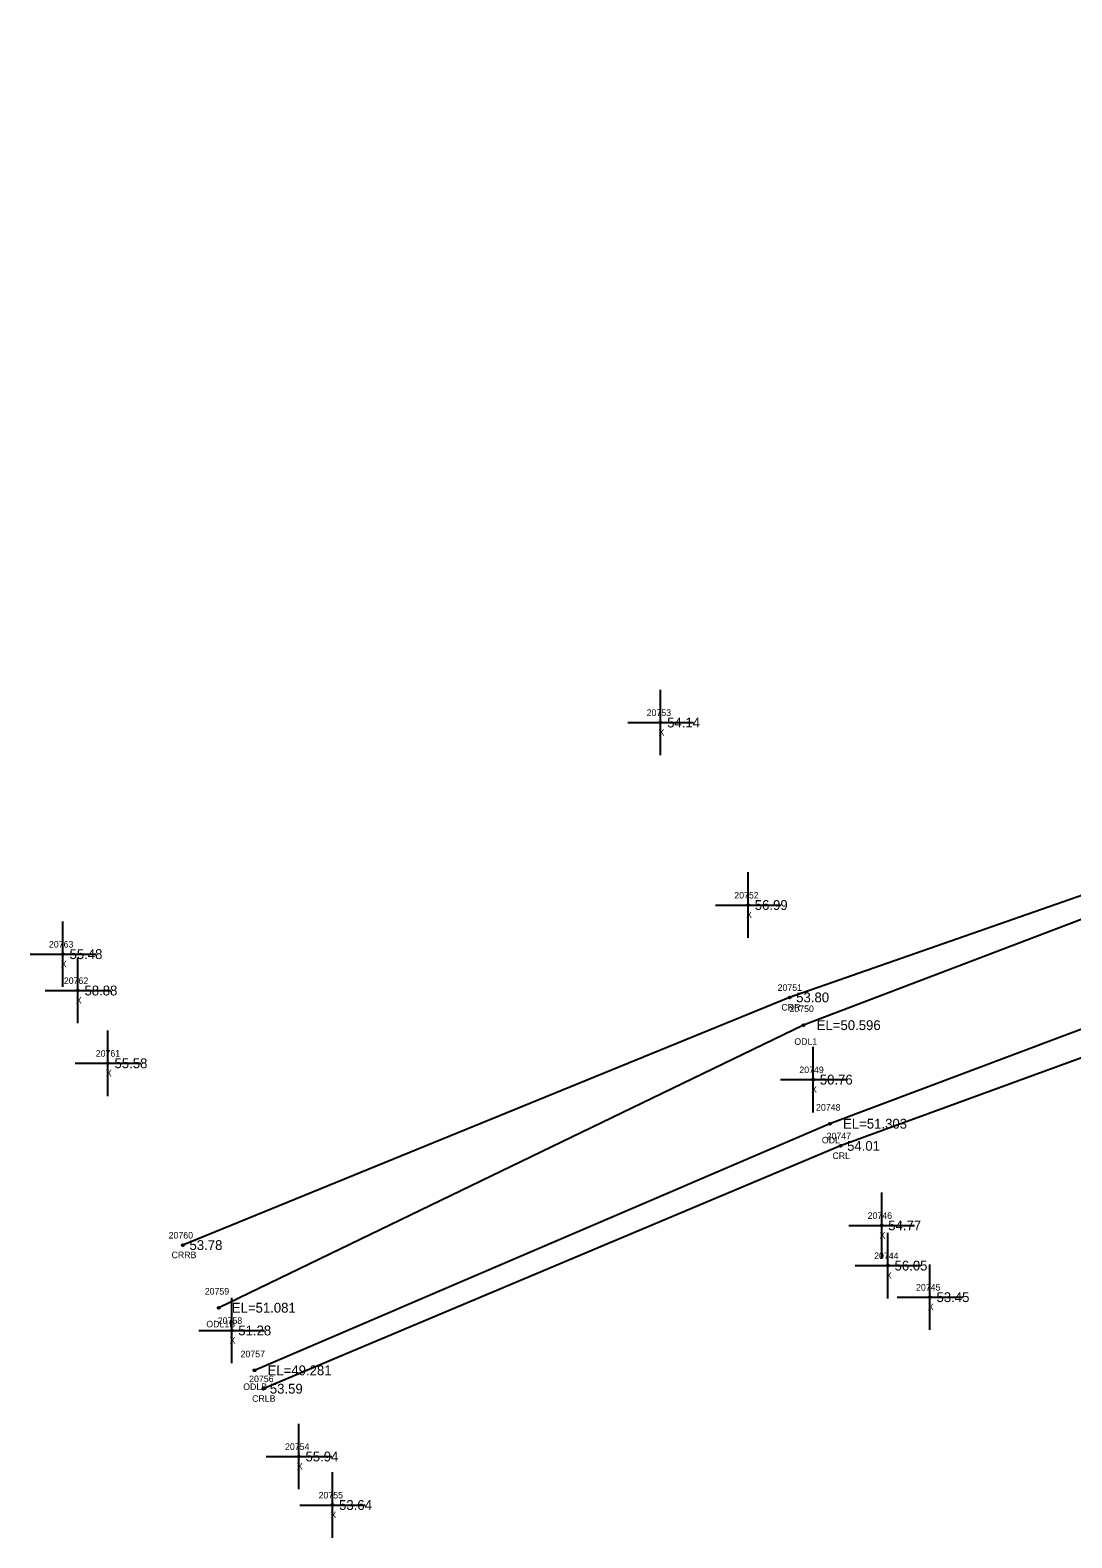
# Model space of a CAD drawing. Extents: x 2396547 to 2397655, y 770185 to 772649.
# Drawn here: x 2396546.9 to 2396705.8, y 771163.5 to 771393.4 of the extents above; entities that cross this region are included whole.
import ezdxf

# ---------------------------------------------------------------- set-up
doc = ezdxf.new("R2010")
doc.units = 0
for name, color, linetype in [('RD_EX_H2O', 7, 'Continuous'), ('RD_EX_H2O_txCode', 7, 'Continuous'), ('RD_EX_Misc', 7, 'Continuous'), ('RD_EX_Misc_txCode', 7, 'Continuous'), ('RD_EX_TX_H2O_ELEV', 7, 'Continuous'), ('RD_EX_TX_Misc_ELEV', 7, 'Continuous'), ('RD_SMD_Locator', 7, 'Continuous')]:
    doc.layers.add(name, color=color, linetype=linetype)

msp = doc.modelspace()

# ---------------------------------------------------------------- linework, layer by layer
at = {"layer": 'RD_EX_H2O'}
for points in [[(2397026.41, 771393.39), (2397025.73, 771381.74), (2396981.24, 771369.21), (2396933.35, 771351.16), (2396867.1, 771327.21), (2396805.16, 771301.5), (2396726.77, 771268.25), (2396662.72, 771245.88), (2396570.19, 771208.11)], [(2397042.3, 771381.6), (2397026.95, 771379.1), (2396982.27, 771366.23), (2396935.45, 771345.14), (2396869.6, 771319.67), (2396806.56, 771295.91), (2396727.11, 771265.36), (2396664.85, 771241.65), (2396575.64, 771198.56)], [(2397029.25, 771363), (2396987.12, 771353.36), (2396940.53, 771333.19), (2396876.37, 771307.51), (2396813.23, 771283.31), (2396732.14, 771250.38), (2396668.87, 771226.62), (2396581.1, 771189.01)], [(2397041.52, 771355.95), (2397038.66, 771356.79), (2397028.89, 771358.5), (2397025.33, 771358.42), (2397018.97, 771356.22), (2396990.02, 771346.89), (2396942.55, 771327.39), (2396877.94, 771304.58), (2396814.23, 771281.47), (2396733.01, 771246.09), (2396670.48, 771223.24), (2396582.44, 771186.21)]]:
    msp.add_lwpolyline(points, dxfattribs=at)
at = {"layer": 'RD_EX_Misc'}
for p, q in [((2396643.04, 771282.8), (2396643.04, 771292.8)), ((2396638.04, 771287.8), (2396648.04, 771287.8)), ((2396656.4, 771254.97), (2396656.4, 771264.97)), ((2396651.4, 771259.97), (2396661.4, 771259.97)), ((2396551.89, 771247.48), (2396551.89, 771257.48)), ((2396546.89, 771252.48), (2396556.89, 771252.48)), ((2396554.17, 771241.93), (2396554.17, 771251.93)), ((2396549.17, 771246.93), (2396559.17, 771246.93)), ((2396558.75, 771230.84), (2396558.75, 771240.84)), ((2396666.32, 771228.34), (2396666.32, 771238.34)), ((2396553.75, 771235.84), (2396563.75, 771235.84)), ((2396661.32, 771233.34), (2396671.32, 771233.34)), ((2396676.76, 771206.11), (2396676.76, 771216.11)), ((2396671.76, 771211.11), (2396681.76, 771211.11)), ((2396677.72, 771199.98), (2396677.72, 771209.98)), ((2396672.72, 771204.98), (2396682.72, 771204.98)), ((2396684.12, 771195.17), (2396684.12, 771205.17)), ((2396577.63, 771190.09), (2396577.63, 771200.09)), ((2396679.12, 771200.17), (2396689.12, 771200.17)), ((2396572.63, 771195.09), (2396582.63, 771195.09)), ((2396587.88, 771170.87), (2396587.88, 771180.87)), ((2396582.88, 771175.87), (2396592.88, 771175.87)), ((2396593, 771163.47), (2396593, 771173.47)), ((2396588, 771168.47), (2396598, 771168.47))]:
    msp.add_line(p, q, dxfattribs=at)
at = {"layer": 'RD_SMD_Locator'}
for centre in [(2396643.04, 771287.8), (2396656.4, 771259.97), (2396551.89, 771252.48), (2396554.17, 771246.93), (2396662.72, 771245.88), (2396664.85, 771241.65), (2396558.75, 771235.84), (2396666.32, 771233.34), (2396668.87, 771226.62), (2396670.48, 771223.24), (2396676.76, 771211.11), (2396570.19, 771208.11), (2396677.72, 771204.98), (2396684.12, 771200.17), (2396575.64, 771198.56), (2396577.63, 771195.09), (2396581.1, 771189.01), (2396582.44, 771186.21), (2396587.88, 771175.87), (2396593, 771168.47)]:
    msp.add_circle(centre, 0.15, dxfattribs=at)

# ---------------------------------------------------------------- texts
at = {"layer": 'RD_EX_H2O_txCode'}
for s, p in [('20751', (2396660.89, 771246.88)), ('CRR', (2396661.47, 771243.88)), ('20750', (2396662.7, 771243.65)), ('ODL1', (2396663.44, 771238.65)), ('20748', (2396666.75, 771228.62)), ('ODL', (2396667.63, 771223.62)), ('20747', (2396668.36, 771224.24)), ('CRL', (2396669.25, 771221.24)), ('20760', (2396568.01, 771209.11)), ('CRRB', (2396568.46, 771206.11)), ('20759', (2396573.52, 771200.56)), ('ODL1B', (2396573.76, 771195.56)), ('20757', (2396578.98, 771191.01)), ('20756', (2396580.29, 771187.21)), ('ODLB', (2396579.38, 771186.01)), ('CRLB', (2396580.74, 771184.21))]:
    msp.add_text(s, height=1, dxfattribs=at).set_placement(p)
at = {"layer": 'RD_EX_Misc_txCode'}
for s, p in [('20753', (2396640.92, 771288.8)), ('X', (2396642.72, 771285.8)), ('20752', (2396654.28, 771260.97)), ('X', (2396656.09, 771257.97)), ('20763', (2396549.75, 771253.48)), ('X', (2396551.57, 771250.48)), ('20762', (2396552.03, 771247.93)), ('X', (2396553.86, 771244.93)), ('20761', (2396556.89, 771236.84)), ('X', (2396558.43, 771233.84)), ('20749', (2396664.2, 771234.34)), ('X', (2396666, 771231.34)), ('20746', (2396674.62, 771212.11)), ('X', (2396676.44, 771209.11)), ('20744', (2396675.61, 771205.98)), ('X', (2396677.41, 771202.98)), ('20745', (2396682, 771201.17)), ('20758', (2396575.51, 771196.09)), ('X', (2396683.8, 771198.17)), ('X', (2396577.31, 771193.09)), ('20754', (2396585.76, 771176.87)), ('X', (2396587.56, 771173.87)), ('20755', (2396590.88, 771169.47)), ('X', (2396592.68, 771166.47))]:
    msp.add_text(s, height=1, dxfattribs=at).set_placement(p)
at = {"layer": 'RD_EX_TX_H2O_ELEV'}
for s, p in [('53.80', (2396663.72, 771245.13)), ('EL=50.596', (2396666.85, 771240.9)), ('EL=51.303', (2396670.87, 771225.87)), ('54.01', (2396671.48, 771222.49)), ('53.78', (2396571.19, 771207.36)), ('EL=51.081', (2396577.64, 771197.81)), ('EL=49.281', (2396583.1, 771188.26)), ('53.59', (2396583.44, 771185.46))]:
    msp.add_text(s, height=1.5, dxfattribs=at).set_placement(p)
at = {"layer": 'RD_EX_TX_Misc_ELEV'}
for s, p in [('54.14', (2396644.04, 771287.05)), ('56.99', (2396657.4, 771259.22)), ('55.48', (2396552.89, 771251.73)), ('58.88', (2396555.17, 771246.18)), ('55.58', (2396559.75, 771235.09)), ('50.76', (2396667.32, 771232.59)), ('54.77', (2396677.76, 771210.36)), ('56.05', (2396678.72, 771204.23)), ('53.45', (2396685.12, 771199.42)), ('51.28', (2396578.63, 771194.34)), ('55.94', (2396588.88, 771175.12)), ('53.64', (2396594, 771167.72))]:
    msp.add_text(s, height=1.5, dxfattribs=at).set_placement(p)

doc.saveas('drawing.dxf')
